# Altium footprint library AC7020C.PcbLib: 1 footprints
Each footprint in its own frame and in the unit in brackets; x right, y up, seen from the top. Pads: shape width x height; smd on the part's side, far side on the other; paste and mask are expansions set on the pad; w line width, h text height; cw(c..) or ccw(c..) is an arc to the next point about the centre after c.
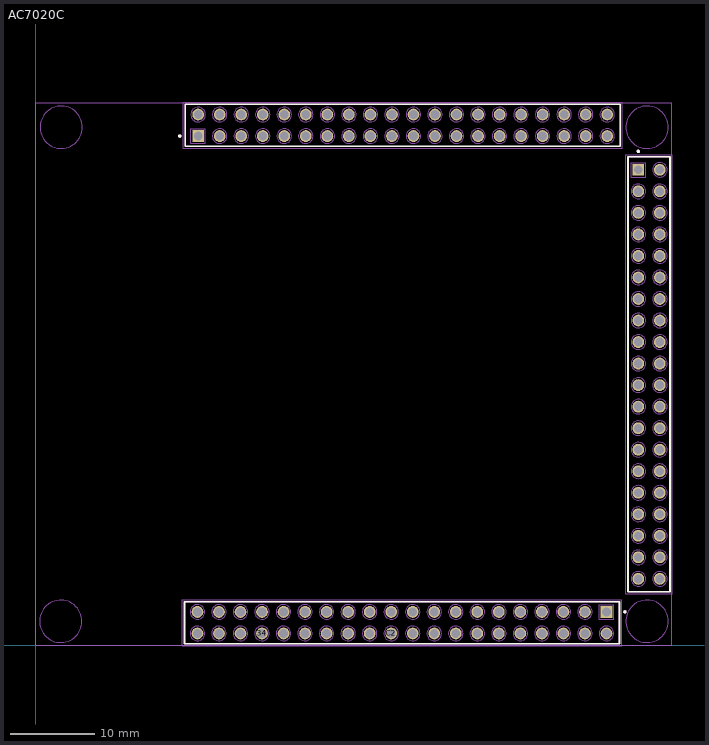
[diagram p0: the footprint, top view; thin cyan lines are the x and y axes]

## AC7020C [mm]
pads (120):
  round 1.39 hole 1.04 mask+0.102: 34(26.69,1.388) A02(19.157,62.608) A03(21.697,60.068) A04(21.697,62.608) A05(24.237,60.068) A06(24.237,62.608) A07(26.777,60.068) A08(26.777,62.608) A09(29.317,60.068) A10(29.317,62.608) A11(31.857,60.068) A12(31.857,62.608) A13(34.397,60.068) A14(34.397,62.608) A15(36.937,60.068) A16(36.937,62.608) A17(39.477,60.068) A18(39.477,62.608) A19(42.017,60.068) A20(42.017,62.608) A21(44.557,60.068) A22(44.557,62.608) A23(47.097,60.068) A24(47.097,62.608) A25(49.637,60.068) A26(49.637,62.608) A27(52.177,60.068) A28(52.177,62.608) A29(54.717,60.068) A30(54.717,62.608) A31(57.257,60.068) A32(57.257,62.608) A33(59.797,60.068) A34(59.797,62.608) A35(62.337,60.068) A36(62.337,62.608) A37(64.877,60.068) A38(64.877,62.608) A39(67.417,60.068) A40(67.417,62.608) B02(73.622,56.087) B03(71.082,53.547) B04(73.622,53.547) B05(71.082,51.007) B06(73.622,51.007) B07(71.082,48.467) B08(73.622,48.467) B09(71.082,45.927) B10(73.622,45.927) B11(71.082,43.387) B12(73.622,43.387) B13(71.082,40.847) B14(73.622,40.847) B15(71.082,38.307) B16(73.622,38.307) B17(71.082,35.767) B18(73.622,35.767) B19(71.082,33.227) B20(73.622,33.227) B21(71.082,30.687) B22(73.622,30.687) B23(71.082,28.147) B24(73.622,28.147) B25(71.082,25.607) B26(73.622,25.607) B27(71.082,23.067) B28(73.622,23.067) B29(71.082,20.527) B30(73.622,20.527) B31(71.082,17.987) B32(73.622,17.987) B33(71.082,15.447) B34(73.622,15.447) B35(71.082,12.907) B36(73.622,12.907) B37(71.082,10.367) B38(73.622,10.367) B39(71.082,7.827) B40(73.622,7.827) C2(41.93,1.388) C02(67.33,1.388) C03(64.79,3.928) C04(64.79,1.388) C05(62.25,3.928) C06(62.25,1.388) C07(59.71,3.928) C08(59.71,1.388) C09(57.17,3.928) C10(57.17,1.388) C11(54.63,3.928) C12(54.63,1.388) C13(52.09,3.928) C14(52.09,1.388) C15(49.55,3.928) C16(49.55,1.388) C17(47.01,3.928) C18(47.01,1.388) C19(44.47,3.928) C20(44.47,1.388) C21(41.93,3.928) C23(39.39,3.928) C24(39.39,1.388) C25(36.85,3.928) C26(36.85,1.388) C27(34.31,3.928) C28(34.31,1.388) C29(31.77,3.928) C30(31.77,1.388) C31(29.23,3.928) C32(29.23,1.388) C33(26.69,3.928) C35(24.15,3.928) C36(24.15,1.388) C37(21.61,3.928) C38(21.61,1.388) C39(19.07,3.928) C40(19.07,1.388)
  rect 1.39x1.39 / inner round 1.39 / far side rect 1.39x1.39 hole 1.04 mask+0.102: A01(19.157,60.068) B01(71.082,56.087) C01(67.33,3.928)
Top Overlay:
  circle w0.2: c69.505,3.928 r0.1
  circle w0.2: c71.082,58.262 r0.1
  circle w0.2: c16.982,60.068 r0.1
  lines w0.2: 17.545,0.181 17.545,5.134 68.855,5.134 68.855,0.181 17.545,0.181 ; 17.632,58.861 17.632,63.814 68.942,63.814 68.942,58.861 17.632,58.861 ; 69.876,6.302 74.829,6.302 74.829,57.612 69.876,57.612 69.876,6.302
Mechanical 13:
  circle w0.2: c69.505,3.928 r0.1
  circle w0.2: c71.082,58.262 r0.1
  circle w0.2: c16.982,60.068 r0.1
  lines w0.1: 17.545,0.181 17.545,5.134 ; 17.545,0.181 68.855,0.181 ; 17.545,0.181 17.545,5.134 ; 17.545,0.181 68.855,0.181 ; 17.545,5.134 68.855,5.134 ; 17.632,58.861 17.632,63.814 ; 17.632,58.861 68.942,58.861 ; 17.632,58.861 17.632,63.814 ; 17.632,63.814 68.942,63.814 ; 17.632,63.814 68.942,63.814 ; 68.855,0.181 68.855,5.134 ; 68.855,0.181 68.855,5.134 ; 68.942,58.861 68.942,63.814 ; 68.942,58.861 68.942,63.814 ; 69.876,6.302 74.829,6.302 ; 69.876,6.302 69.876,57.612 ; 69.876,6.302 74.829,6.302 ; 69.876,57.612 74.829,57.612 ; 69.876,57.612 74.829,57.612 ; 74.829,6.302 74.829,57.612 ; 74.829,6.302 74.829,57.612
Mechanical 15:
  circle w0.013: c2.946,2.819 r2.5
  circle w0.013: c72.111,2.819 r2.5
  circle w0.013: c72.111,61.112 r2.5
  circle w0.013: c2.997,61.112 r2.5
  circle w0.013: c73.624,56.086 r0.864
  circle w0.013: c71.084,53.546 r0.864
  circle w0.013: c73.624,53.546 r0.864
  circle w0.013: c71.084,51.006 r0.864
  circle w0.013: c73.624,51.006 r0.864
  circle w0.013: c71.084,48.466 r0.864
  circle w0.013: c73.624,48.466 r0.864
  circle w0.013: c71.084,45.926 r0.864
  circle w0.013: c73.624,45.926 r0.864
  circle w0.013: c71.084,43.386 r0.864
  circle w0.013: c73.624,43.386 r0.864
  circle w0.013: c71.084,40.846 r0.864
  circle w0.013: c73.624,40.846 r0.864
  circle w0.013: c71.084,38.306 r0.864
  circle w0.013: c73.624,38.306 r0.864
  circle w0.013: c71.084,35.766 r0.864
  circle w0.013: c73.624,35.766 r0.864
  circle w0.013: c71.084,33.226 r0.864
  circle w0.013: c73.624,33.226 r0.864
  circle w0.013: c71.084,30.686 r0.864
  circle w0.013: c73.624,30.686 r0.864
  circle w0.013: c71.084,28.146 r0.864
  circle w0.013: c73.624,28.146 r0.864
  circle w0.013: c71.084,25.606 r0.864
  circle w0.013: c73.624,25.606 r0.864
  circle w0.013: c71.084,23.066 r0.864
  circle w0.013: c73.624,23.066 r0.864
  circle w0.013: c71.084,20.526 r0.864
  circle w0.013: c73.624,20.526 r0.864
  circle w0.013: c71.084,17.986 r0.864
  circle w0.013: c73.624,17.986 r0.864
  circle w0.013: c71.084,15.446 r0.864
  circle w0.013: c73.624,15.446 r0.864
  circle w0.013: c71.084,12.906 r0.864
  circle w0.013: c73.624,12.906 r0.864
  circle w0.013: c71.084,10.366 r0.864
  circle w0.013: c73.624,10.366 r0.864
  circle w0.013: c71.084,7.826 r0.864
  circle w0.013: c73.624,7.826 r0.864
  circle w0.013: c67.325,1.387 r0.864
  circle w0.013: c64.785,3.927 r0.864
  circle w0.013: c64.785,1.387 r0.864
  circle w0.013: c62.245,3.927 r0.864
  circle w0.013: c62.245,1.387 r0.864
  circle w0.013: c59.705,3.927 r0.864
  circle w0.013: c59.705,1.387 r0.864
  circle w0.013: c57.165,3.927 r0.864
  circle w0.013: c57.165,1.387 r0.864
  circle w0.013: c54.625,3.927 r0.864
  circle w0.013: c54.625,1.387 r0.864
  circle w0.013: c52.085,3.927 r0.864
  circle w0.013: c52.085,1.387 r0.864
  circle w0.013: c49.545,3.927 r0.864
  circle w0.013: c49.545,1.387 r0.864
  circle w0.013: c47.005,3.927 r0.864
  circle w0.013: c47.005,1.387 r0.864
  circle w0.013: c44.465,3.927 r0.864
  circle w0.013: c44.465,1.387 r0.864
  circle w0.013: c41.925,3.927 r0.864
  circle w0.013: c41.925,1.387 r0.864
  circle w0.013: c39.385,3.927 r0.864
  circle w0.013: c39.385,1.387 r0.864
  circle w0.013: c36.845,3.927 r0.864
  circle w0.013: c36.845,1.387 r0.864
  circle w0.013: c34.305,3.927 r0.864
  circle w0.013: c34.305,1.387 r0.864
  circle w0.013: c31.765,3.927 r0.864
  circle w0.013: c31.765,1.387 r0.864
  circle w0.013: c29.225,3.927 r0.864
  circle w0.013: c29.225,1.387 r0.864
  circle w0.013: c26.685,3.927 r0.864
  circle w0.013: c26.685,1.387 r0.864
  circle w0.013: c24.145,3.927 r0.864
  circle w0.013: c24.145,1.387 r0.864
  circle w0.013: c21.605,3.927 r0.864
  circle w0.013: c21.605,1.387 r0.864
  circle w0.013: c19.065,3.927 r0.864
  circle w0.013: c19.065,1.387 r0.864
  circle w0.013: c19.149,62.608 r0.864
  circle w0.013: c21.689,60.068 r0.864
  circle w0.013: c21.689,62.608 r0.864
  circle w0.013: c24.229,60.068 r0.864
  circle w0.013: c24.229,62.608 r0.864
  circle w0.013: c26.769,60.068 r0.864
  circle w0.013: c26.769,62.608 r0.864
  circle w0.013: c29.309,60.068 r0.864
  circle w0.013: c29.309,62.608 r0.864
  circle w0.013: c31.849,60.068 r0.864
  circle w0.013: c31.849,62.608 r0.864
  circle w0.013: c34.389,60.068 r0.864
  circle w0.013: c34.389,62.608 r0.864
  circle w0.013: c36.929,60.068 r0.864
  circle w0.013: c36.929,62.608 r0.864
  circle w0.013: c39.469,60.068 r0.864
  circle w0.013: c39.469,62.608 r0.864
  circle w0.013: c42.009,60.068 r0.864
  circle w0.013: c42.009,62.608 r0.864
  circle w0.013: c44.549,60.068 r0.864
  circle w0.013: c44.549,62.608 r0.864
  circle w0.013: c47.089,60.068 r0.864
  circle w0.013: c47.089,62.608 r0.864
  circle w0.013: c49.629,60.068 r0.864
  circle w0.013: c49.629,62.608 r0.864
  circle w0.013: c52.169,60.068 r0.864
  circle w0.013: c52.169,62.608 r0.864
  circle w0.013: c54.709,60.068 r0.864
  circle w0.013: c54.709,62.608 r0.864
  circle w0.013: c57.249,60.068 r0.864
  circle w0.013: c57.249,62.608 r0.864
  circle w0.013: c59.789,60.068 r0.864
  circle w0.013: c59.789,62.608 r0.864
  circle w0.013: c62.329,60.068 r0.864
  circle w0.013: c62.329,62.608 r0.864
  circle w0.013: c64.869,60.068 r0.864
  circle w0.013: c64.869,62.608 r0.864
  circle w0.013: c67.409,60.068 r0.864
  circle w0.013: c67.409,62.608 r0.864
  lines w0.013: 0,0 75,0 75,64 0,64 0,0 ; 18.285,59.205 18.285,60.932 20.013,60.932 20.013,59.205 18.285,59.205 ; 66.462,3.063 68.189,3.063 68.189,4.79 66.462,4.79 66.462,3.063 ; 70.221,55.222 71.948,55.222 71.948,56.949 70.221,56.949 70.221,55.222
  lines w0.05: 17.295,-0.069 17.295,5.384 69.105,5.384 69.105,-0.069 17.295,-0.069 ; 17.382,58.611 17.382,64.064 69.192,64.064 69.192,58.611 17.382,58.611 ; 69.626,6.052 75.079,6.052 75.079,57.862 69.626,57.862 69.626,6.052
3D body "AC7020C_3D.STEP": height 23.66, standoff 4.23, extent -0.205,0.062 74.795,64.062
3D body "AC7020.STEP": height 8.51, standoff -3.15, extent 17.477,0.288 68.785,5.241
3D body "AC7020.STEP": height 8.51, standoff -3.15, extent 69.899,6.234 74.852,57.542
3D body "AC7020.STEP": height 8.51, standoff -3.15, extent 17.719,58.894 69.027,63.847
